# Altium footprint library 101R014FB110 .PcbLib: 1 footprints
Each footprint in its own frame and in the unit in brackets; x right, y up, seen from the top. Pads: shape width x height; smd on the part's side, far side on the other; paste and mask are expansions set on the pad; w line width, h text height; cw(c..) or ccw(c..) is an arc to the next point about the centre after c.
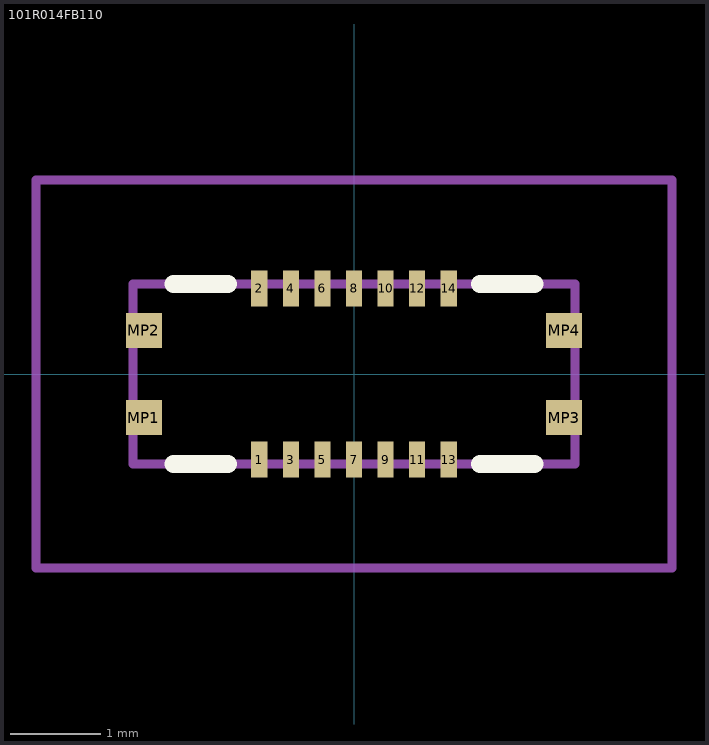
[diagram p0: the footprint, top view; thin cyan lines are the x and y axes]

## 101R014FB110 [mm] "14pins + 2 power paths"
height 1
pads (18):
  rect 0.18x0.4 smd: 1(-1.05,-0.95) 2(-1.05,0.95) 3(-0.7,-0.95) 4(-0.7,0.95) 5(-0.35,-0.95) 6(-0.35,0.95) 7(0,-0.95) 8(0,0.95) 9(0.35,-0.95) 10(0.35,0.95) 11(0.7,-0.95) 12(0.7,0.95) 13(1.05,-0.95) 14(1.05,0.95)
  rect 0.4x0.385 smd: MP1(-2.33,-0.483) MP2(-2.33,0.483) MP3(2.33,-0.483) MP4(2.33,0.483)
Top Overlay:
  lines w0.2: -2,-1 -1.4,-1 ; -2,1 -1.4,1 ; 1.4,-1 2,-1 ; 1.4,1 2,1
Mechanical 13:
  lines w0.1: -2.45,-1 -2.45,1 2.45,1 2.45,-1 -2.45,-1
Mechanical 15:
  lines w0.1: -3.53,-2.15 -3.53,2.15 3.53,2.15 3.53,-2.15 -3.53,-2.15
3D body "101R014FB110.stp": height 0.78, standoff 0, extent -2.45,-0.995 2.45,1.005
